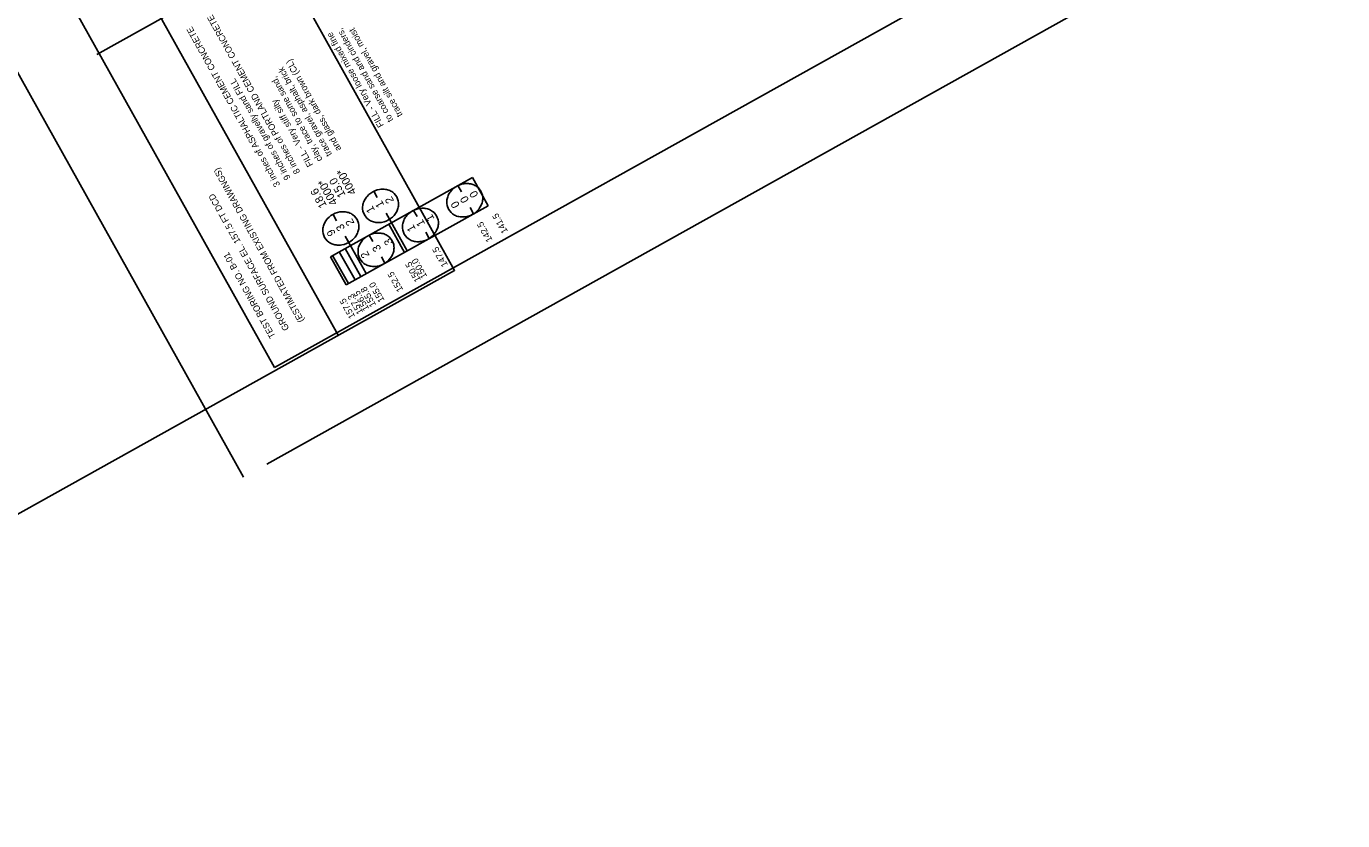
# Model space of a CAD drawing. Extents: x 13482447 to 13495412, y 324533 to 340229.
# Drawn here: x 13492545 to 13493524, y 329986 to 330577 of the extents above; entities that cross this region are included whole.
import ezdxf

# ---------------------------------------------------------------- set-up
doc = ezdxf.new("R2010")
doc.units = 0
for name, color, linetype in [('Default', 7, 'Continuous'), ('DETAIL_TEXT_DIMEN_PR', 7, 'Continuous'), ('Level 1', 7, 'Continuous'), ('Level 63', 7, 'Continuous'), ('TYPICAL_TEXT_DIMEN_PR', 7, 'Continuous')]:
    doc.layers.add(name, color=color, linetype=linetype)

# ---------------------------------------------------------------- blocks, each defined once
blk = doc.blocks.new('DGRFC_BLOW$COUNT$ELLIPSE')
at = {"layer": 'Default'}
blk.add_lwpolyline([(0, -0.0274), (0.0061, -0.0265), (0.0089, -0.0254), (0.0104, -0.0246), (0.0118, -0.0238), (0.0132, -0.0228), (0.0145, -0.0218), (0.0157, -0.0206), (0.0168, -0.0194), (0.0179, -0.018), (0.0189, -0.0167), (0.0198, -0.0152), (0.0206, -0.0137), (0.0213, -0.0122), (0.022, -0.0106), (0.023, -0.0071), (0.0236, -0.0036), (0.0238, 0), (0.0236, 0.0036), (0.023, 0.0071), (0.022, 0.0106), (0.0213, 0.0122), (0.0206, 0.0137), (0.0198, 0.0152), (0.0189, 0.0167), (0.0179, 0.018), (0.0168, 0.0194), (0.0157, 0.0206), (0.0145, 0.0218), (0.0132, 0.0228), (0.0118, 0.0238), (0.0104, 0.0246), (0.0089, 0.0254), (0.0061, 0.0265), (0, 0.0274), (-0.0061, 0.0265), (-0.0089, 0.0254), (-0.0104, 0.0246), (-0.0118, 0.0238), (-0.0132, 0.0228), (-0.0145, 0.0218), (-0.0157, 0.0206), (-0.0168, 0.0194), (-0.0179, 0.018), (-0.0189, 0.0167), (-0.0198, 0.0152), (-0.0206, 0.0137), (-0.0213, 0.0122), (-0.022, 0.0106), (-0.023, 0.0071), (-0.0236, 0.0036), (-0.0238, 0), (-0.0236, -0.0036), (-0.023, -0.0071), (-0.022, -0.0106), (-0.0213, -0.0122), (-0.0206, -0.0137), (-0.0198, -0.0152), (-0.0189, -0.0167), (-0.0179, -0.018), (-0.0168, -0.0194), (-0.0157, -0.0206), (-0.0145, -0.0218), (-0.0132, -0.0228), (-0.0118, -0.0238), (-0.0104, -0.0246), (-0.0089, -0.0254), (-0.0061, -0.0265), (0, -0.0274)], dxfattribs=at)

msp = doc.modelspace()

# ---------------------------------------------------------------- linework, layer by layer
at = {"layer": 'Default'}
for points in [[(13493219.69, 330902.86), (13492597.3, 330555.58)], [(13492771.11, 330405.23), (13492876.67, 330464.14)], [(13492771.11, 330405.23), (13492876.67, 330464.14)], [(13492888.37, 330443.18), (13492876.67, 330464.14)], [(13492888.37, 330443.18), (13492876.67, 330464.14)], [(13492782.8, 330384.28), (13492888.37, 330443.18)], [(13492782.8, 330384.28), (13492888.37, 330443.18)], [(13492826.14, 330408.46), (13492814.45, 330429.42)], [(13492789.4, 330387.96), (13492777.7, 330408.92)], [(13492793.82, 330390.42), (13492782.12, 330411.38)], [(13492782.8, 330384.28), (13492771.11, 330405.23)], [(13492782.8, 330384.28), (13492771.11, 330405.23)], [(13492784.45, 330385.2), (13492772.75, 330406.15)], [(13492784.45, 330385.2), (13492772.75, 330406.15)]]:
    msp.add_lwpolyline(points, dxfattribs=at)
at = {"layer": 'Level 1'}
for p, q in [((13492706.35, 330241.19), (13492006.65, 331495.19)), ((13492729.51, 330322.82), (13492088.28, 331472.03)), ((13493459.55, 330730.17), (13492729.51, 330322.82)), ((13493523.72, 330697.26), (13492723.81, 330250.94))]:
    msp.add_line(p, q, dxfattribs=at)
at = {"layer": 'Level 63'}
msp.add_lwpolyline([(13492129.81, 329985.73), (13491486.63, 331138.43), (13492220.17, 331547.72), (13492863.35, 330395.02)], close=True, dxfattribs=at)
at = {"layer": 'TYPICAL_TEXT_DIMEN_PR'}
for p, q in [((13492776.8, 330346.93), (13492382.64, 331053.32)), ((13492868.53, 330453.44), (13492865.94, 330458.09)), ((13492805.97, 330449.27), (13492803.38, 330453.92)), ((13492775.64, 330432), (13492773.04, 330436.65)), ((13492815.02, 330433.05), (13492812.43, 330437.69)), ((13492828.17, 330409.49), (13492812.43, 330437.69)), ((13492835.54, 330435.04), (13492832.95, 330439.68)), ((13492877.58, 330437.22), (13492874.99, 330441.87)), ((13492784.69, 330415.78), (13492782.1, 330420.43)), ((13492797.6, 330392.64), (13492782.1, 330420.43)), ((13492802.55, 330416.63), (13492799.96, 330421.27)), ((13492844.59, 330418.81), (13492842, 330423.46)), ((13492811.6, 330400.41), (13492809.01, 330405.05))]:
    msp.add_line(p, q, dxfattribs=at)

# ---------------------------------------------------------------- block references
at = {"layer": 'Default', "xscale": 503.9370078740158, "yscale": 503.93700787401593, "rotation": 119.16052892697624}
for p in [(13492808.41, 330443.04), (13492808.41, 330443.04), (13492870.97, 330447.22), (13492870.97, 330447.22), (13492778.84, 330426.26), (13492778.84, 330426.26), (13492837.98, 330428.81), (13492837.98, 330428.81), (13492804.99, 330410.4), (13492804.99, 330410.4)]:
    msp.add_blockref('DGRFC_BLOW$COUNT$ELLIPSE', p, dxfattribs=at)

# ---------------------------------------------------------------- texts
at = {"layer": 'Default'}
for s, height, p in [('4000*', 5.952, (13492790.62, 330453.12)), ('4000*', 5.952, (13492790.62, 330453.12)), (' 18.6', 5.952, (13492769.66, 330441.43)), (' 18.6', 5.952, (13492769.66, 330441.43)), ('4000*', 5.952, (13492776.65, 330445.33)), ('4000*', 5.952, (13492776.65, 330445.33)), (' 15.0', 5.952, (13492783.63, 330449.23)), (' 15.0', 5.952, (13492783.63, 330449.23)), ('1', 5.95, (13492811.31, 330443.62)), ('2', 5.95, (13492818.62, 330446.8)), ('0', 5.95, (13492867.48, 330443.43)), ('0', 5.95, (13492874.41, 330447.29)), ('0', 5.95, (13492881.34, 330451.16)), ('1', 5.95, (13492804.38, 330439.75)), ('1', 5.95, (13492848.59, 330433.51)), ('3', 5.95, (13492782.18, 330426.38)), ('3', 5.95, (13492782.18, 330426.38)), ('2', 5.95, (13492789.16, 330430.28)), ('2', 5.95, (13492789.16, 330430.28)), ('1', 5.95, (13492834.73, 330425.78)), ('1', 5.95, (13492841.66, 330429.65)), ('9', 5.95, (13492775.19, 330422.49)), ('9', 5.95, (13492775.19, 330422.49)), ('3', 5.95, (13492817.77, 330415.79)), ('2', 5.95, (13492800.44, 330406.13)), ('3', 5.95, (13492809.11, 330410.96))]:
    msp.add_text(s, height=height, rotation=119.16053, dxfattribs=at).set_placement(p)
at = {"layer": 'DETAIL_TEXT_DIMEN_PR'}
for s, p in [('8 inches of PORTLAND CEMENT CONCRETE', (13492748.8, 330468.26)), ('3 inches of ASPHALTIC CEMENT CONCRETE', (13492733.93, 330458.75)), ('to coarse sand and cinders, ', (13492818, 330506.87)), ('trace silt and gravel, moist', (13492824.99, 330510.77)), ('FILL - Very loose mixed fine ', (13492811.01, 330502.97)), ('trace gravel, asphalt, brick ', (13492772.39, 330481.42)), ('and glass, dark brown (CL)', (13492779.38, 330485.32)), ('9 inches of gravelly sand FILL', (13492741.59, 330463.83)), ('clay, trace to some sand, ', (13492765.41, 330477.52)), ('FILL - Very stiff silty ', (13492758.42, 330473.62)), ('(ESTIMATED FROM EXISTING DRAWINGS)', (13492751.73, 330357.95)), ('GROUND SURFACE EL. 157.5 FT DCD', (13492740.65, 330351.77)), ('141.5', (13492903.16, 330424.06)), ('142.5', (13492891.78, 330417.72)), ('TEST BORING NO. B-01', (13492730.47, 330346.08)), ('147.5', (13492858.56, 330399.18)), ('150.5', (13492838.49, 330387.98)), ('150.0', (13492843.18, 330390.6)), ('152.5', (13492825.34, 330380.65)), ('156.5', (13492800.05, 330366.53)), ('155.8', (13492805.2, 330369.41)), ('155.0', (13492811.5, 330372.92)), ('157.5', (13492789.66, 330360.74)), ('157.3', (13492795.51, 330364))]:
    msp.add_text(s, height=4.8, rotation=119.16053, dxfattribs=at).set_placement(p)

doc.saveas('drawing.dxf')
